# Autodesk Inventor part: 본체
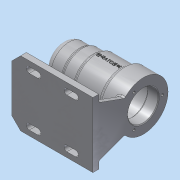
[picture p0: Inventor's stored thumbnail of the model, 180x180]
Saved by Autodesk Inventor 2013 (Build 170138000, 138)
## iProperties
Created: 2017-09
Part Number: 본체
Material: 알루미늄 6061
Document SubType Name: Modeling
Designer: dgall
Density: 2.71 g/cm^3
Mass: 697.905 g
Surface Area: 709.142 cm^2
Volume: 257.529 cm^3
Author: dgall
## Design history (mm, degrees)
sketch "스케치1"
  geometry: L1 (0, 0)-(112, 0); L2 (0, 0)-(0, 25); L3 (0, 25)-(25, 25); L4 (25, 25)-(25, 27); L5 (25, 27)-(45, 27); L6 (45, 27)-(45, 30); L7 (45, 30)-(84, 30); L8 (84, 30)-(84, 34); L9 (84, 34)-(112, 34); L10 (112, 34)-(112, 0)
  constraints: 20 end point, 6 parallel, 2 perpendicular, 1 horizontal, 1 vertical
  dimensions: "d0" = 25 distance of L2.end L3.end; "d2" = 45 distance between parallel lines of L6 L2; "d3" = 84 distance between parallel lines of L8 L2; "d4" = 112 distance between parallel lines of L10 L2; "d5" = 50 diameter of L3 L1; "d6" = 54 diameter of L5 L1; "d7" = 60 diameter of L7 L1; "d8" = 68 diameter of L9 L1
revolve "회전1" sketch "스케치1" stored, may be unused: angle "d9" = 90 deg
node "작업 평면9"
  node "작업 평면8"
sketch "스케치7"
  geometry: L1 (-112, 34)-(-112, -34) reference; L2 (-112, 45)-(0, 45); L3 (0, 45)-(0, -45); L4 (0, -45)-(-112, -45); L5 (-112, -45)-(-112, 45); 2 further points
  constraints: 8 end point, 2 parallel, 1 horizontal, 1 horizontal alignment, 1 midpoint, 1 perpendicular, 1 point on line
  dimensions: "d21" = 90 distance of L4.end L2.start; "d23" = 112 distance of L2.start L2.end; "d24" = 45 distance of L2.start point (-112, 0)
extrude "돌출1" join sketch "스케치7" distance "d25" = 8; taper "d26" = 0 deg
sketch "스케치8"
  geometry: L1 (45, -62)-(-45, -62) reference; L2 (-35, -62)-(-21.9, -26.008); L3 (35, -62)-(21.9, -26.008); L4 (-45, -70)-(-45, -62) reference; L5 (45, -70)-(45, -62) reference; L6 (-35, -62)-(35, -62); C1 r 34 at (0, 0) reference; A1 r 34 centre (0, 0) between (-21.9, -26.008) and (21.9, -26.008) reference; A2 r 49.136 centre (0, 17.978) between (-21.9, -26.008) and (21.9, -26.008)
  constraints: 6 end point, 4 point on circle, 1 centre point, 1 equal length, 1 point on line
  dimensions: "d29" = 10 distance from line of L5 L3.start; "d31" = 110 deg angle of L2 L1; "d32" = 110 deg angle of L1 L3; "d33" = 10 distance from line of L2.start L4; "d34" = 49.13585 radius of A2
extrude "돌출2" join sketch "스케치8" distance "d35" = 8; taper "d36" = 0 deg
node "작업 평면10"
sketch "스케치9"
  geometry: L1 (112, -62)-(0, -62) reference; L2 (25, -27)-(45, -27) reference; L3 (22, -62)-(31.378, -27); L4 (112, -62)-(112, -26.008) reference; L5 (22, -62)-(104, -62); L6 (31.378, -27)-(32.372, -23.292); L7 (32.372, -23.292)-(104, -23.292); L8 (104, -23.292)-(104, -62); 2 further points
  constraints: 10 end point, 2 point on line, 1 collinear, 1 parallel, 1 perpendicular
  dimensions: "d37" = 105 deg angle of L3 L1; "d38" = 22 distance of L1.end L3.start; "d41" = 71.62817 distance of L6.end L7.end
extrude "돌출3" join sketch "스케치9" stored distance "d39" = 8; taper "d40" = 0 deg
sketch "스케치10"
  geometry: L1 (0, 0)-(112, 0); L2 (112, -26.008)-(112, 34) reference; L3 (112, 0)-(112, 21); L4 (112, 21)-(97, 21); L5 (97, 21)-(97, 24); L6 (97, 24)-(43, 24); L7 (43, 24)-(43, 21); L8 (43, 21)-(31, 21); L9 (31, 21)-(31, 17.5); L10 (31, 17.5)-(13, 17.5); L11 (13, 17.5)-(13, 16); L12 (13, 16)-(9, 16); L13 (9, 16)-(9, 10.5); L14 (9, 10.5)-(9, 10.5); L15 (6, 7.5)-(6, 0); A1 r 3 centre (9, 7.5) between (9, 10.5) and (6, 7.5); 1 further point
  constraints: 28 end point, 7 parallel, 5 point on line, 3 perpendicular, 2 point on circle, 2 tangent, 1 centre point, 1 collinear, 1 horizontal, 1 vertical
  dimensions: "d42" = 3 distance of L13.end point (6, 10.5); "d44" = 21 diameter of L14 L1; "d45" = 32 diameter of L12 L1; "d46" = 4 distance of L11.end L12.end; "d47" = 18 distance of L9.end L10.end; "d48" = 35 diameter of L10 L1; "d49" = 12 distance of L7.end L8.end; "d50" = 42 diameter of L8 L1; "d51" = 48 diameter of L6 L1; "d52" = 42 diameter of L4 L1; "d53" = 15 distance of L3.end L4.end; "d54" = 54 distance of L5.end L6.end; "d120" = 3 radius of A1
revolve "회전2" sketch "스케치10" stored, may be unused: angle "d55" = 90 deg
fillet "모깎기1" dims "d56" = 9
sketch "스케치11"
  geometry: L1 (80, 8)-(90, 8) reference; L2 (45, 70)-(22.483, 57); L3 (45, 70)-(67.517, 57); L4 (45, 70)-(45, 96); L5 (45, 70)-(45, 96); A1 r 34 centre (45, 70) between (66.9, 43.992) and (23.1, 43.992) reference; A2 r 26 centre (45, 70) between (45, 96) and (22.483, 57); 1 further point
  constraints: 8 end point, 3 point on circle, 2 coincident, 1 centre point, 1 collinear, 1 perpendicular
  dimensions: "d59" = 52 diameter of A2; "d61" = 120 deg angle of L4 L2; "d63" = 120 deg angle of L4 L3
hole "구멍1" sketch "스케치11" at (22.483, 57) diameter "d64" = 3.459; stored, may be unused: countersink angle "d68" = 90 deg, drill point angle "d70" = 118 deg; dims "d65" = 8, "d66" = 4, "d67" = 2, "d69" = 11
chamfer "모따기1" distance "d74" = 12; stored, may be unused: second distance "d75" = 2, angle "d76" = 45 deg
sketch "스케치13"
  geometry: L1 (112, -45)-(112, -35) reference; L2 (112, 45)-(12, 45) reference; L3 (88, -30)-(76, -30); L4 (88, -38)-(76, -38); L5 (36, -30)-(24, -30); L6 (36, -38)-(24, -38); A1 r 4 centre (88, -34) between (88, -38) and (88, -30); A2 r 4 centre (76, -34) between (76, -30) and (76, -38); A3 r 4 centre (36, -34) between (36, -38) and (36, -30); A4 r 4 centre (24, -34) between (24, -30) and (24, -38); 1 further point
  constraints: 8 end point, 8 point on circle, 8 tangent, 4 centre point, 4 parallel, 1 horizontal alignment
  dimensions: "d80" = 24 distance from line of L1 A1.centre; "d81" = 12 distance of A2.centre A1.centre; "d82" = 8 distance between parallel lines of L3 L4; "d83" = 34 vertical distance of point (0, 0) A2.centre; "d84" = 40 distance of A3.centre A2.centre; "d85" = 8 diameter of A3; "d86" = 12 distance of A3.centre A4.centre
extrude "돌출4" cut sketch "스케치13" stored distance "d87" = 8; taper "d88" = 0 deg
extrude "돌출5" cut sketch "스케치13" distance "d89" = 8; taper "d90" = 0 deg
node "작업 평면11"
sketch "스케치14"
  geometry: L1 (112, -26.008)-(112, 34) reference; 2 further points
  constraints: 1 horizontal alignment, 1 other
  dimensions: "d92" = 48 distance from line of L1 point (64, 0)
feature "엠보싱1" sketch "스케치14" dims "d0" = 25, "d2" = 45, "d3" = 84, "d4" = 112, "d5" = 50, "d6" = 54, "d7" = 60, "d8" = 68, "d25" = 8, "d26" = 0, "d93" = 0.5, "d94" = 0
chamfer "모따기2" distance "d101" = 1; stored, may be unused: second distance "d102" = 2, angle "d103" = 45 deg
fillet "모깎기9" dims "d105" = 0.3
fillet "모깎기11" dims "d107" = 3
fillet "모깎기19" dims "d115" = 3
fillet "모깎기20" dims "d116" = 3
fillet "모깎기21" dims "d117" = 3
fillet "모깎기22" dims "d118" = 3
fillet "모깎기23" dims "d119" = 3
node "솔리드1"
pattern_circular "원형 패턴1" dims angle "d72" = 360 deg
mirror "대칭1"
other parameters: "d91" = 351
